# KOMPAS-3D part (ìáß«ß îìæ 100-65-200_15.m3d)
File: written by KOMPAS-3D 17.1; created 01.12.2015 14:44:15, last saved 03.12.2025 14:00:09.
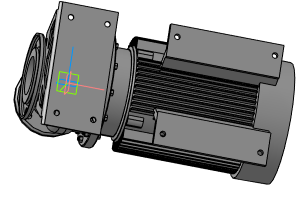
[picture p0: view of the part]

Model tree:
1. Операция без истории:4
